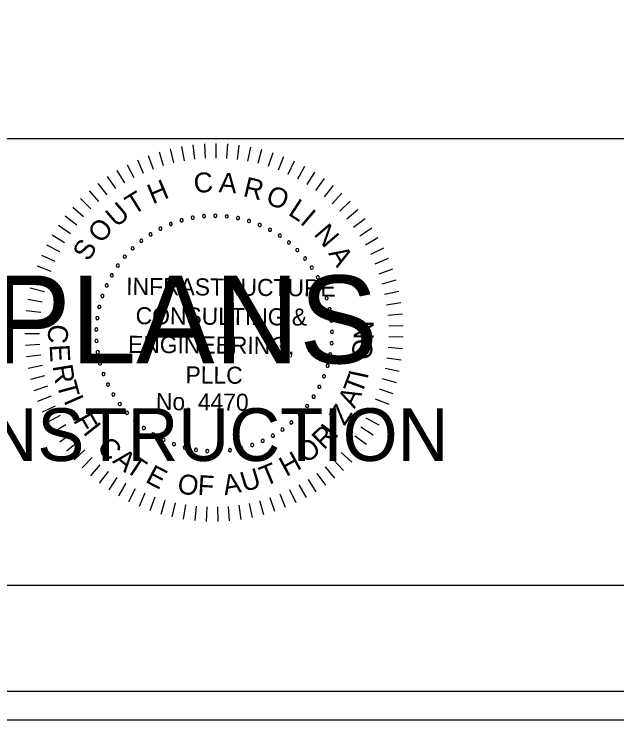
# Model space of a CAD drawing. Extents: x 967 to 1326, y 964 to 2304.
# Drawn here: x 1189.3 to 1212.88, y 963.72 to 991.36 of the extents above; entities that cross this region are included whole.
import ezdxf

# ---------------------------------------------------------------- set-up
doc = ezdxf.new("R2010")
doc.units = 0
for name, color, linetype in [('RD_PD_PaveShd', 7, 'Continuous'), ('RD_XS_Misc_Line', 7, 'Continuous'), ('RD_XS_PaveOvlay', 7, 'Continuous'), ('RD_XS_TX_Elev_EX', 7, 'Continuous'), ('RD_XS_TX_Elev_PR', 7, 'Continuous')]:
    doc.layers.add(name, color=color, linetype=linetype)

msp = doc.modelspace()

# ---------------------------------------------------------------- linework, layer by layer
at = {"layer": 'RD_PD_PaveShd'}
for p, q in [((996.114, 986.486), (1323.886, 986.486)), ((1323.886, 968.983), (996.114, 968.983))]:
    msp.add_line(p, q, dxfattribs=at)
at = {"layer": 'RD_XS_Misc_Line'}
for p, q in [((1196.292, 986.245), (1196.357, 985.68)), ((1196.742, 986.282), (1196.772, 985.714)), ((1197.194, 986.292), (1197.189, 985.723)), ((1197.645, 986.274), (1197.606, 985.706)), ((1198.094, 986.228), (1198.02, 985.664)), ((1194.968, 985.971), (1195.134, 985.427)), ((1195.403, 986.09), (1195.536, 985.536)), ((1195.846, 986.181), (1195.945, 985.62)), ((1198.54, 986.156), (1198.432, 985.596)), ((1198.98, 986.056), (1198.838, 985.504)), ((1199.414, 985.929), (1199.238, 985.387)), ((1194.122, 985.656), (1194.353, 985.136)), ((1194.54, 985.827), (1194.739, 985.293)), ((1199.839, 985.777), (1199.63, 985.246)), ((1193.715, 985.461), (1193.978, 984.956)), ((1200.253, 985.598), (1200.013, 985.082)), ((1200.656, 985.395), (1200.385, 984.894)), ((1193.321, 985.241), (1193.614, 984.752)), ((1201.047, 985.167), (1200.745, 984.684)), ((1192.94, 984.997), (1193.263, 984.528)), ((1201.422, 984.917), (1201.092, 984.453)), ((1192.576, 984.731), (1192.926, 984.282)), ((1201.781, 984.643), (1201.424, 984.2)), ((1192.228, 984.443), (1192.605, 984.016)), ((1202.124, 984.349), (1201.739, 983.928)), ((1191.899, 984.134), (1192.301, 983.731)), ((1202.447, 984.034), (1202.038, 983.638)), ((1191.589, 983.805), (1192.015, 983.428)), ((1202.751, 983.7), (1202.318, 983.329)), ((1191.299, 983.459), (1191.748, 983.108)), ((1203.034, 983.348), (1202.579, 983.004)), ((1191.032, 983.095), (1191.501, 982.772)), ((1203.294, 982.979), (1202.82, 982.664)), ((1190.787, 982.716), (1191.274, 982.422)), ((1203.532, 982.595), (1203.04, 982.31)), ((1190.565, 982.323), (1191.07, 982.059)), ((1203.746, 982.198), (1203.237, 981.943)), ((1190.368, 981.916), (1190.888, 981.684)), ((1203.936, 981.788), (1203.412, 981.564)), ((1190.196, 981.499), (1190.729, 981.299)), ((1204.1, 981.367), (1203.563, 981.176)), ((1190.05, 981.072), (1190.594, 980.905)), ((1204.238, 980.937), (1203.691, 980.779)), ((1189.93, 980.636), (1190.484, 980.503)), ((1204.349, 980.5), (1203.794, 980.375)), ((1189.837, 980.195), (1190.398, 980.095)), ((1204.434, 980.056), (1203.872, 979.966)), ((1189.771, 979.748), (1190.337, 979.683)), ((1204.491, 979.608), (1203.925, 979.552)), ((1189.732, 979.298), (1190.301, 979.267)), ((1204.522, 979.158), (1203.953, 979.137)), ((1189.721, 978.847), (1190.29, 978.851)), ((1204.524, 978.706), (1203.955, 978.72)), ((1189.737, 978.396), (1190.306, 978.434)), ((1204.499, 978.256), (1203.932, 978.304)), ((1189.781, 977.946), (1190.346, 978.019)), ((1204.447, 977.807), (1203.884, 977.89)), ((1189.852, 977.5), (1190.412, 977.608)), ((1204.367, 977.363), (1203.81, 977.479)), ((1189.951, 977.06), (1190.502, 977.201)), ((1204.261, 976.924), (1203.712, 977.074)), ((1190.076, 976.626), (1190.617, 976.8)), ((1204.128, 976.492), (1203.589, 976.676)), ((1190.227, 976.2), (1190.757, 976.408)), ((1203.969, 976.07), (1203.442, 976.286)), ((1190.403, 975.785), (1190.92, 976.024)), ((1203.784, 975.658), (1203.271, 975.906)), ((1190.605, 975.381), (1191.106, 975.651)), ((1203.574, 975.258), (1203.078, 975.537)), ((1190.831, 974.99), (1191.315, 975.291)), ((1203.341, 974.871), (1202.862, 975.18)), ((1191.081, 974.614), (1191.545, 974.943)), ((1191.353, 974.253), (1191.796, 974.61)), ((1203.085, 974.5), (1202.626, 974.837)), ((1202.806, 974.145), (1202.368, 974.509)), ((1191.646, 973.91), (1192.067, 974.293)), ((1202.506, 973.807), (1202.092, 974.197)), ((1191.96, 973.585), (1192.356, 973.994)), ((1202.186, 973.488), (1201.796, 973.903)), ((1192.293, 973.28), (1192.664, 973.712)), ((1201.847, 973.19), (1201.484, 973.628)), ((1192.644, 972.996), (1192.988, 973.45)), ((1193.011, 972.734), (1193.327, 973.208)), ((1201.491, 972.912), (1201.155, 973.372)), ((1193.394, 972.495), (1193.68, 972.987)), ((1200.731, 972.425), (1200.453, 972.922)), ((1201.119, 972.657), (1200.811, 973.136)), ((1193.791, 972.279), (1194.047, 972.788)), ((1200.331, 972.217), (1200.083, 972.73)), ((1194.2, 972.088), (1194.424, 972.612)), ((1194.62, 971.923), (1194.812, 972.459)), ((1199.495, 971.877), (1199.312, 972.416)), ((1199.918, 972.034), (1199.702, 972.561)), ((1195.05, 971.783), (1195.208, 972.33)), ((1195.487, 971.67), (1195.612, 972.225)), ((1195.93, 971.584), (1196.021, 972.146)), ((1196.377, 971.524), (1196.434, 972.091)), ((1198.179, 971.562), (1198.097, 972.126)), ((1198.624, 971.64), (1198.508, 972.198)), ((1199.063, 971.745), (1198.913, 972.295)), ((1196.828, 971.493), (1196.85, 972.062)), ((1197.279, 971.488), (1197.267, 972.058)), ((1197.73, 971.512), (1197.683, 972.079))]:
    msp.add_line(p, q, dxfattribs=at)
for centre, start, end in [((1196.285, 983.388), 10.6038, 190.6038), ((1196.727, 983.447), 5.0653, 185.0653), ((1196.727, 983.447), 185.0653, 5.0653), ((1197.172, 983.464), 359.5268, 179.5268), ((1197.172, 983.464), 179.5268, 359.5268), ((1197.617, 983.438), 173.9884, 353.9884), ((1197.617, 983.438), 353.9884, 173.9884), ((1198.057, 983.369), 348.4499, 168.4499), ((1195.429, 983.142), 21.6807, 201.6807), ((1195.429, 983.142), 201.6807, 21.6807), ((1195.851, 983.285), 16.1422, 196.1422), ((1195.851, 983.285), 196.1422, 16.1422), ((1196.285, 983.388), 190.6038, 10.6038), ((1198.057, 983.369), 168.4499, 348.4499), ((1198.489, 983.258), 162.9114, 342.9114), ((1198.489, 983.258), 342.9114, 162.9114), ((1198.908, 983.106), 337.373, 157.373), ((1195.023, 982.958), 27.2191, 207.2191), ((1195.023, 982.958), 207.2191, 27.2191), ((1198.908, 983.106), 157.373, 337.373), ((1199.31, 982.914), 151.8345, 331.8345), ((1199.31, 982.914), 331.8345, 151.8345), ((1194.637, 982.736), 32.7576, 212.7576), ((1194.637, 982.736), 212.7576, 32.7576), ((1199.692, 982.684), 146.2961, 326.2961), ((1199.692, 982.684), 326.2961, 146.2961), ((1194.274, 982.478), 38.2961, 218.2961), ((1194.274, 982.478), 218.2961, 38.2961), ((1200.05, 982.419), 140.7576, 320.7576), ((1200.05, 982.419), 320.7576, 140.7576), ((1193.937, 982.186), 43.8345, 223.8345), ((1193.937, 982.186), 223.8345, 43.8345), ((1200.38, 982.12), 135.2191, 315.2191), ((1200.38, 982.12), 315.2191, 135.2191), ((1193.63, 981.862), 49.373, 229.373), ((1193.63, 981.862), 229.373, 49.373), ((1200.68, 981.79), 129.6807, 309.6807), ((1200.68, 981.79), 309.6807, 129.6807), ((1193.356, 981.511), 54.9114, 234.9114), ((1193.356, 981.511), 234.9114, 54.9114), ((1200.947, 981.433), 304.1422, 124.1422), ((1200.947, 981.433), 124.1422, 304.1422), ((1193.117, 981.135), 60.4499, 240.4499), ((1193.117, 981.135), 240.4499, 60.4499), ((1201.179, 981.052), 118.6038, 298.6038), ((1201.179, 981.052), 298.6038, 118.6038), ((1192.915, 980.737), 65.9884, 245.9884), ((1192.915, 980.737), 245.9884, 65.9884), ((1201.372, 980.651), 113.0653, 293.0653), ((1201.372, 980.651), 293.0653, 113.0653), ((1192.753, 980.322), 71.5268, 251.5268), ((1192.753, 980.322), 251.5268, 71.5268), ((1201.526, 980.233), 107.5268, 287.5268), ((1201.526, 980.233), 287.5268, 107.5268), ((1192.632, 979.894), 77.0653, 257.0653), ((1192.632, 979.894), 257.0653, 77.0653), ((1201.638, 979.801), 101.9884, 281.9884), ((1201.638, 979.801), 281.9884, 101.9884), ((1192.552, 979.455), 82.6038, 262.6038), ((1192.552, 979.455), 262.6038, 82.6038), ((1201.709, 979.361), 96.4499, 276.4499), ((1201.709, 979.361), 276.4499, 96.4499), ((1192.515, 979.011), 88.1422, 268.1422), ((1192.515, 979.011), 268.1422, 88.1422), ((1201.737, 978.917), 90.9114, 270.9114), ((1201.737, 978.917), 270.9114, 90.9114), ((1192.522, 978.565), 93.6807, 273.6807), ((1192.522, 978.565), 273.6807, 93.6807), ((1201.721, 978.471), 85.373, 265.373), ((1201.721, 978.471), 265.373, 85.373), ((1192.571, 978.122), 99.2191, 279.2191), ((1192.571, 978.122), 279.2191, 99.2191), ((1201.663, 978.029), 79.8345, 259.8345), ((1201.663, 978.029), 259.8345, 79.8345), ((1192.662, 977.686), 104.7576, 284.7576), ((1192.662, 977.686), 284.7576, 104.7576), ((1201.563, 977.595), 74.2961, 254.2961), ((1201.563, 977.595), 254.2961, 74.2961), ((1192.796, 977.261), 110.2961, 290.2961), ((1192.796, 977.261), 290.2961, 110.2961), ((1201.42, 977.173), 68.7576, 248.7576), ((1201.42, 977.173), 248.7576, 68.7576), ((1192.97, 976.851), 115.8345, 295.8345), ((1192.97, 976.851), 295.8345, 115.8345), ((1201.238, 976.766), 63.2191, 243.2191), ((1201.238, 976.766), 243.2191, 63.2191), ((1193.182, 976.459), 301.373, 121.373), ((1193.182, 976.459), 121.373, 301.373), ((1201.018, 976.379), 57.6807, 237.6807), ((1201.018, 976.379), 237.6807, 57.6807), ((1193.432, 976.09), 126.9114, 306.9114), ((1193.432, 976.09), 306.9114, 126.9114), ((1200.761, 976.014), 52.1422, 232.1422), ((1200.761, 976.014), 232.1422, 52.1422), ((1193.715, 975.746), 132.4499, 312.4499), ((1193.715, 975.746), 312.4499, 132.4499), ((1200.47, 975.677), 46.6038, 226.6038), ((1200.47, 975.677), 226.6038, 46.6038), ((1194.031, 975.431), 137.9884, 317.9884), ((1194.031, 975.431), 317.9884, 137.9884), ((1200.148, 975.369), 41.0653, 221.0653), ((1200.148, 975.369), 221.0653, 41.0653), ((1194.376, 975.149), 143.5268, 323.5268), ((1194.376, 975.149), 323.5268, 143.5268), ((1199.798, 975.093), 35.5268, 215.5268), ((1194.746, 974.901), 149.0653, 329.0653), ((1194.746, 974.901), 329.0653, 149.0653), ((1199.422, 974.853), 29.9884, 209.9884), ((1199.422, 974.853), 209.9884, 29.9884), ((1199.798, 975.093), 215.5268, 35.5268), ((1195.139, 974.69), 154.6038, 334.6038), ((1195.139, 974.69), 334.6038, 154.6038), ((1195.55, 974.517), 340.1422, 160.1422), ((1199.026, 974.65), 24.4499, 204.4499), ((1199.026, 974.65), 204.4499, 24.4499), ((1195.55, 974.517), 160.1422, 340.1422), ((1195.975, 974.386), 165.6807, 345.6807), ((1195.975, 974.386), 345.6807, 165.6807), ((1196.412, 974.295), 171.2191, 351.2191), ((1196.412, 974.295), 351.2191, 171.2191), ((1196.855, 974.248), 356.7576, 176.7576), ((1197.301, 974.243), 2.2961, 182.2961), ((1197.745, 974.282), 7.8345, 187.8345), ((1198.183, 974.363), 13.373, 193.373), ((1198.183, 974.363), 193.373, 13.373), ((1198.611, 974.486), 18.9114, 198.9114), ((1198.611, 974.486), 198.9114, 18.9114), ((1196.855, 974.248), 176.7576, 356.7576), ((1197.301, 974.243), 182.2961, 2.2961), ((1197.745, 974.282), 187.8345, 7.8345)]:
    msp.add_arc(centre, 0.0627, start, end, dxfattribs=at)
at = {"layer": 'RD_XS_PaveOvlay'}
msp.add_lwpolyline([(967.409, 963.72), (1326.285, 963.72), (1326.285, 1183.72), (967.409, 1183.72)], close=True, dxfattribs=at)
at = {"layer": 'RD_XS_TX_Elev_EX'}
for points in [[(967.409, 963.72), (1326.285, 963.72), (1326.285, 1183.72), (967.409, 1183.72)], [(988.525, 964.84), (1326.285, 964.84), (1326.285, 1182.6), (988.525, 1182.6)]]:
    msp.add_lwpolyline(points, close=True, dxfattribs=at)

# ---------------------------------------------------------------- texts
at = {"layer": 'RD_XS_Misc_Line'}
for s, height, rotation, p in [('C', 0.78, 4.7281, (1196.355, 984.346)), ('A', 0.78, 355.6981, (1197.29, 984.39)), ('H', 0.78, 22.7882, (1194.72, 983.904)), ('R', 0.78, 346.6681, (1198.222, 984.238)), ('O', 0.78, 337.638, (1199.096, 983.972)), ('T', 0.78, 31.8182, (1193.961, 983.478)), ('U', 0.78, 40.8482, (1193.306, 982.976)), ('L', 0.78, 327.108, (1199.981, 983.52)), ('I', 0.78, 319.578, (1200.451, 983.182)), ('O', 0.78, 49.8782, (1192.707, 982.341)), ('N', 0.78, 310.548, (1200.994, 982.728)), ('S', 0.78, 58.9083, (1192.211, 981.642)), ('A', 0.78, 301.5179, (1201.576, 981.991)), ('INFRASTRUCTURE', 0.66873, 359.5268, (1193.682, 980.367)), ('CONSULTING &', 0.66873, 359.5268, (1194.051, 979.217)), ('N', 0.78, 89.2085, (1203.359, 978.604)), ('C', 0.78, 267.025, (1190.646, 979.227)), ('ENGINEERING,', 0.66873, 359.5268, (1193.751, 978.095)), ('O', 0.78, 83.2085, (1203.26, 977.786)), ('E', 0.78, 273.025, (1190.685, 978.408)), ('R', 0.78, 279.025, (1190.799, 977.583)), ('PLLC', 0.6687, 359.5268, (1196.002, 976.9)), ('I', 0.78, 77.9093, (1203.121, 977.032)), ('T', 0.78, 69.3954, (1202.891, 976.428)), ('T', 0.78, 285.025, (1190.955, 976.878)), ('No. 4470', 0.6687, 359.5268, (1194.843, 975.855)), ('A', 0.78, 63.3954, (1202.616, 975.888)), ('I', 0.78, 293.7713, (1191.221, 976.225)), ('Z', 0.78, 57.3954, (1202.224, 975.206)), ('F', 0.78, 299.7713, (1191.589, 975.455)), ('I', 0.78, 308.5268, (1191.965, 974.973)), ('R', 0.78, 44.5268, (1201.415, 974.267)), ('I', 0.78, 52.3339, (1201.856, 974.69)), ('C', 0.78, 314.5268, (1192.496, 974.346)), ('O', 0.78, 38.5268, (1200.73, 973.731)), ('A', 0.78, 320.5268, (1193.115, 973.822)), ('T', 0.78, 326.5268, (1193.602, 973.478)), ('H', 0.78, 28.5268, (1199.942, 973.23)), ('T', 0.78, 22.5268, (1199.108, 972.856)), ('E', 0.78, 332.5268, (1194.394, 973.051)), ('U', 0.78, 16.5268, (1198.288, 972.638)), ('O', 0.78, 350.5268, (1195.647, 972.614)), ('F', 0.78, 356.5268, (1196.465, 972.532)), ('A', 0.78, 10.5268, (1197.537, 972.517))]:
    msp.add_text(s, height=height, rotation=rotation, dxfattribs=at).set_placement(p)
at = {"layer": 'RD_XS_TX_Elev_PR'}
for s, height, p in [('FINAL PLANS', 3.4375, (1174.145, 977.685)), ('NOT FOR CONSTRUCTION', 2.0625, (1170.901, 973.86))]:
    msp.add_text(s, height=height, dxfattribs=at).set_placement(p)

doc.saveas('drawing.dxf')
